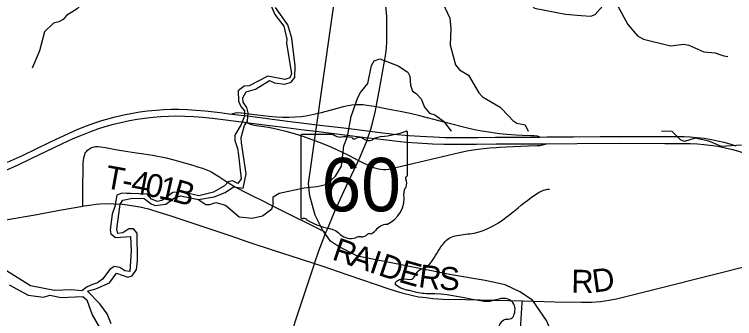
# Model space of a CAD drawing. Extents: x 0 to 34, y 0 to 22.
# Drawn here: x 4.8 to 6.577, y 15.488 to 16.238 of the extents above; entities that cross this region are included whole.
import ezdxf

# ---------------------------------------------------------------- set-up
doc = ezdxf.new("R2010")
doc.units = 0
for name, color, linetype in [('GM_X_County_Road', 7, 'Continuous'), ('GM_X_County_Road_Text', 7, 'Continuous'), ('GM_X_Interchange_Ramps', 7, 'Continuous'), ('GM_X_Minor_River', 7, 'Continuous'), ('GM_X_Rail_Line', 7, 'Continuous'), ('GM_X_State_Location', 7, 'Continuous'), ('GM_X_State_Route', 7, 'Continuous'), ('GM_X_State_Shield', 7, 'Continuous'), ('GM_X_Township_Road', 7, 'Continuous'), ('GM_X_Township_Road_Text', 7, 'Continuous')]:
    doc.layers.add(name, color=color, linetype=linetype)

msp = doc.modelspace()

# ---------------------------------------------------------------- linework, layer by layer
at = {"layer": 'GM_X_County_Road'}
for points in [[(4.2337, 15.6322), (4.2931, 15.6431), (4.4857, 15.6775), (4.6018, 15.6992), (4.6966, 15.7158), (4.7485, 15.7255), (4.7882, 15.7329), (4.8463, 15.7434), (4.9165, 15.7564), (4.9688, 15.7656)], [(4.9688, 15.7656), (4.9722, 15.7662), (4.9911, 15.769), (5.0017, 15.7704), (5.0113, 15.771), (5.0239, 15.7716), (5.0456, 15.7714), (5.0672, 15.7701), (5.0783, 15.7688), (5.0884, 15.7674), (5.0996, 15.7655), (5.1101, 15.7637), (5.1312, 15.7588), (5.141, 15.7557), (5.1518, 15.7525), (5.1861, 15.7413), (5.3317, 15.6927), (5.3758, 15.6777), (5.4436, 15.6552), (5.5029, 15.6367), (5.5408, 15.6243)], [(6.0536, 15.5319), (6.1339, 15.5298), (6.1992, 15.5286), (6.2241, 15.529), (6.2458, 15.5306), (6.2674, 15.5335), (6.2888, 15.5378), (6.3973, 15.5647), (6.6263, 15.6221), (6.7469, 15.6522), (6.8373, 15.6746), (6.913, 15.6935)], [(5.5408, 15.6243), (5.559, 15.6184), (5.6205, 15.5966), (5.7265, 15.5608), (5.7562, 15.5518), (5.7834, 15.545), (5.7975, 15.5422), (5.808, 15.5408), (5.8218, 15.539), (5.8327, 15.5378), (5.8575, 15.5361), (5.9134, 15.5349), (6.019, 15.5328), (6.0536, 15.5319)], [(6.0456, 15.4154), (6.0457, 15.4174), (6.0482, 15.4483), (6.0533, 15.5269), (6.0536, 15.5319)]]:
    msp.add_lwpolyline(points, dxfattribs=at)
at = {"layer": 'GM_X_Interchange_Ramps'}
for points in [[(5.6926, 16.0099), (5.6819, 16.0118), (5.6697, 16.0139), (5.6604, 16.015), (5.6511, 16.0156), (5.6418, 16.0154), (5.6325, 16.0145), (5.6233, 16.013), (5.6112, 16.0104), (5.5872, 16.0039), (5.5572, 15.9957), (5.5391, 15.9913), (5.5238, 15.9882), (5.5085, 15.9858), (5.493, 15.9844), (5.4775, 15.9838), (5.462, 15.9841), (5.4465, 15.985), (5.4279, 15.9868), (5.386, 15.9916), (5.3602, 15.9949), (5.3515, 15.9955), (5.3453, 15.9947), (5.3366, 15.9924)], [(6.0961, 15.9358), (6.0907, 15.9377), (6.0822, 15.9388), (6.0743, 15.939), (6.0536, 15.9394), (6.0369, 15.9401), (6.0153, 15.9418), (5.9968, 15.9438), (5.9753, 15.9467), (5.9538, 15.9502), (5.9356, 15.9538), (5.9145, 15.9586), (5.8694, 15.9701), (5.8005, 15.9882), (5.7764, 15.994), (5.7521, 15.999), (5.7338, 16.0023), (5.7124, 16.006), (5.6926, 16.0099)], [(5.3737, 15.9714), (5.3799, 15.9682), (5.385, 15.9671), (5.3969, 15.9646), (5.4157, 15.9621), (5.4309, 15.9593), (5.449, 15.9553), (5.47, 15.9501), (5.4908, 15.9443), (5.5115, 15.9379), (5.5319, 15.9308), (5.5522, 15.9232), (5.575, 15.9138), (5.5948, 15.905), (5.6227, 15.8918), (5.6492, 15.878)], [(5.9889, 15.9104), (5.9968, 15.911), (6.031, 15.9127), (6.0683, 15.9138), (6.0898, 15.9147), (6.0962, 15.9151), (6.1031, 15.9162), (6.1065, 15.917), (6.1126, 15.9191)], [(5.6492, 15.878), (5.661, 15.8725), (5.6807, 15.8633), (5.6864, 15.861), (5.6923, 15.859), (5.6983, 15.8575), (5.7045, 15.8565), (5.7106, 15.856), (5.7169, 15.8561), (5.723, 15.8567), (5.7292, 15.8576), (5.7413, 15.8603), (5.7866, 15.8712), (5.8984, 15.8979), (5.9166, 15.9017), (5.9319, 15.9044), (5.9504, 15.9069), (5.972, 15.9091), (5.9889, 15.9104)]]:
    msp.add_lwpolyline(points, dxfattribs=at)
at = {"layer": 'GM_X_Minor_River'}
for points in [[(5.0834, 16.345), (5.0529, 16.3383), (5.0294, 16.3291), (5.003, 16.307), (4.9894, 16.2998), (4.9793, 16.2865), (4.9684, 16.2644), (4.9552, 16.2522), (4.9291, 16.2358), (4.9205, 16.2259), (4.9095, 16.2195), (4.8971, 16.2168), (4.8748, 16.1951), (4.8618, 16.1487), (4.8438, 16.1054)], [(5.8108, 16.3252), (5.8511, 16.2789), (5.8741, 16.2285), (5.8768, 16.2035), (5.8755, 16.1629), (5.8828, 16.1356), (5.8882, 16.1136), (5.8984, 16.1015), (5.9201, 16.0883), (5.9456, 16.0451), (5.9551, 16.0349), (5.9984, 16.0093), (6.0201, 15.987), (6.0296, 15.9764), (6.0398, 15.9703), (6.0599, 15.9662), (6.0676, 15.9499)], [(6.038, 16.3192), (6.065, 16.2743), (6.0837, 16.2539), (6.1598, 16.2386), (6.1981, 16.2353), (6.2223, 16.2339), (6.2333, 16.2377), (6.2521, 16.259), (6.2623, 16.2655), (6.274, 16.267), (6.2884, 16.2599), (6.3136, 16.2129), (6.3372, 16.1857), (6.352, 16.177), (6.4191, 16.1609), (6.452, 16.1648), (6.4641, 16.1626), (6.5013, 16.146), (6.5293, 16.1435), (6.5407, 16.139), (6.5506, 16.136), (6.5604, 16.1341)], [(5.426, 16.277), (5.4425, 16.2376), (5.4649, 16.2089), (5.4726, 16.1767), (5.4719, 16.1672), (5.484, 16.0913), (5.4795, 16.0818), (5.4678, 16.0776), (5.4257, 16.0858), (5.3792, 16.0622), (5.3668, 16.061), (5.3524, 16.0495), (5.3529, 16.0245), (5.3586, 16.0109), (5.3678, 16.0003), (5.3678, 15.9874), (5.3596, 15.9669), (5.3442, 15.9406), (5.3442, 15.9274), (5.3508, 15.9077), (5.3519, 15.8974), (5.3594, 15.833), (5.3515, 15.8215), (5.3382, 15.8276), (5.3276, 15.8253), (5.3186, 15.8157), (5.2918, 15.8001), (5.2555, 15.7905), (5.2134, 15.8006), (5.1915, 15.7994), (5.1658, 15.7803), (5.153, 15.7769), (5.1389, 15.7829)], [(5.0388, 15.4749), (5.0288, 15.5002), (5.0113, 15.5245), (4.9809, 15.5558), (5.0009, 15.5612), (5.035, 15.5765), (5.0519, 15.6001), (5.0803, 15.59), (5.0909, 15.5934), (5.1011, 15.609), (5.104, 15.631), (5.1033, 15.6985), (5.0942, 15.7091), (5.0825, 15.7095), (5.0681, 15.6999), (5.0556, 15.698), (5.0529, 15.7086), (5.061, 15.7705), (5.0674, 15.78), (5.0916, 15.785), (5.1204, 15.7843), (5.1378, 15.7711), (5.1477, 15.7666), (5.1738, 15.7705), (5.1953, 15.7857), (5.2104, 15.7911), (5.2544, 15.7818), (5.2934, 15.7883), (5.3202, 15.7991), (5.3409, 15.8132), (5.3644, 15.8098), (5.3722, 15.8451), (5.3605, 15.9217), (5.3597, 15.935), (5.3683, 15.9639), (5.3754, 15.9753), (5.3773, 15.9958), (5.3738, 16.0083), (5.3643, 16.0219), (5.3638, 16.0325), (5.3717, 16.047), (5.3952, 16.0539), (5.4295, 16.0756), (5.4417, 16.0696), (5.4674, 16.0659), (5.4829, 16.0709), (5.492, 16.0827), (5.4926, 16.1111), (5.4847, 16.1797), (5.4747, 16.2127), (5.4443, 16.2551)], [(5.2524, 15.7822), (5.2726, 15.7697), (5.2825, 15.7693), (5.2976, 15.7743), (5.3207, 15.7676), (5.3545, 15.7389), (5.3871, 15.7359), (5.4124, 15.7417), (5.4351, 15.7585), (5.4388, 15.7691), (5.4387, 15.7881), (5.4538, 15.7972), (5.5151, 15.8107), (5.5473, 15.8135), (5.5722, 15.8193), (5.582, 15.8292), (5.5926, 15.8394), (5.6068, 15.8642), (5.6131, 15.9139), (5.6224, 15.937), (5.6309, 15.9864), (5.6478, 16.0331), (5.6538, 16.0457), (5.6718, 16.0677), (5.6811, 16.1118), (5.6879, 16.1235), (5.7019, 16.1285), (5.747, 16.1112), (5.7709, 16.0961), (5.7755, 16.0859), (5.7771, 16.0635), (5.7821, 16.0487), (5.7916, 16.0435), (5.8041, 16.0299), (5.8118, 16.0094), (5.8243, 15.9943), (5.8376, 15.9905), (5.8585, 15.9747), (5.8775, 15.9504)], [(6.5943, 15.9161), (6.5447, 15.9125), (6.5136, 15.926), (6.4799, 15.9331), (6.4534, 15.9247), (6.4436, 15.9288), (6.4226, 15.9493), (6.3969, 15.9499)], [(5.1389, 15.7829), (5.1279, 15.7946), (5.087, 15.7967), (5.0772, 15.7967), (5.065, 15.7978), (5.0526, 15.7924), (5.0481, 15.7647), (5.0418, 15.7457), (5.0367, 15.7074), (5.0382, 15.6972), (5.0496, 15.6877), (5.0864, 15.6908), (5.0882, 15.655), (5.0852, 15.6044), (5.0727, 15.6059), (5.0605, 15.6138), (5.0461, 15.6168), (5.0359, 15.6095), (5.0179, 15.5856), (5.0054, 15.5764), (4.9933, 15.5718), (4.9797, 15.5665), (4.9665, 15.5562), (4.9408, 15.5587), (4.8988, 15.5575), (4.8397, 15.569), (4.8203, 15.5811), (4.747, 15.6267)], [(4.787, 15.5715), (4.8345, 15.5458), (4.872, 15.5407), (4.8878, 15.5457), (4.9159, 15.5404), (4.9689, 15.5425), (4.9791, 15.5346), (4.9921, 15.4975), (5.028, 15.4346)]]:
    msp.add_lwpolyline(points, dxfattribs=at)
msp.add_spline([(5.6783, 14.4209), (5.6754, 14.4455), (5.659, 14.4864), (5.6554, 14.5103), (5.6393, 14.5702), (5.6236, 14.6069), (5.6144, 14.6437), (5.5991, 14.6824), (5.5748, 14.6842), (5.5627, 14.6803), (5.5472, 14.6814), (5.537, 14.6878), (5.5039, 14.7234), (5.503, 14.737), (5.5034, 14.7518), (5.5108, 14.7826), (5.5096, 14.8019), (5.5173, 14.8585), (5.5353, 14.8885), (5.5764, 14.9217), (5.5881, 14.9323), (5.6085, 14.9567), (5.6099, 14.9817), (5.6832, 15.0036), (5.6759, 15.0453), (5.6722, 15.1143), (5.6743, 15.2396), (5.6809, 15.2885), (5.6899, 15.3106), (5.6985, 15.3235), (5.7094, 15.333), (5.7276, 15.3331), (5.7382, 15.3376), (5.7483, 15.3616), (5.7616, 15.3643), (5.7869, 15.3625), (5.7895, 15.3769), (5.7967, 15.3891), (5.8269, 15.3888), (5.8833, 15.3985), (5.8977, 15.3981), (5.9257, 15.4096), (5.96, 15.4325), (5.9879, 15.4542), (6.0116, 15.4865), (6.0256, 15.4881), (6.0335, 15.4988), (6.0273, 15.5306), (6.0114, 15.5378), (5.9679, 15.53), (5.9547, 15.5311), (5.8376, 15.5489), (5.8028, 15.5507), (5.7774, 15.5567), (5.7679, 15.5586), (5.7406, 15.5763), (5.7557, 15.5862), (5.7807, 15.5851), (5.7991, 15.6076), (5.8142, 15.6141), (5.8248, 15.6229), (5.8526, 15.6651), (5.8764, 15.6883), (5.8923, 15.6933), (5.9343, 15.6991), (6.0268, 15.748), (6.0921, 15.7979), (6.1098, 15.8059), (6.1204, 15.8075)], degree=3, dxfattribs=at)
at = {"layer": 'GM_X_Rail_Line'}
msp.add_lwpolyline([(6.2556, 15.134), (6.2417, 15.1773), (6.1822, 15.3213), (6.1133, 15.4834), (6.0786, 15.5335), (6.047, 15.5543), (6.0111, 15.5713), (5.9614, 15.5818), (5.8784, 15.5959), (5.6469, 15.6419), (5.6002, 15.6656), (5.5803, 15.6787), (5.5601, 15.707), (5.5421, 15.7435), (5.5292, 15.7911), (5.526, 15.8216), (5.5991, 16.337)], dxfattribs=at)
at = {"layer": 'GM_X_State_Route'}
for points in [[(5.719, 16.1697), (5.7194, 16.1783), (5.7192, 16.2219), (5.7187, 16.233), (5.7177, 16.2507), (5.716, 16.2654), (5.7131, 16.2807), (5.709, 16.2957), (5.7037, 16.3104), (5.6933, 16.3346)], [(5.6926, 16.0099), (5.6999, 16.0493), (5.7162, 16.1411), (5.7173, 16.1489), (5.7179, 16.1547), (5.7185, 16.1598), (5.7189, 16.1668), (5.719, 16.1697)], [(5.6693, 15.9259), (5.6725, 15.9341), (5.6778, 15.9501), (5.6795, 15.9551), (5.6846, 15.9731), (5.6909, 16.0004), (5.6926, 16.0099)], [(4.7836, 15.8736), (4.8203, 15.8906), (4.8875, 15.9229), (4.9352, 15.9453), (4.9551, 15.954), (4.9782, 15.9632), (4.9986, 15.9706), (5.0162, 15.9763), (5.0341, 15.9815), (5.0491, 15.9854), (5.0703, 15.9903), (5.0915, 15.9947), (5.1099, 15.9977), (5.1283, 16.0002), (5.1499, 16.0023), (5.1684, 16.0036), (5.187, 16.0042), (5.2056, 16.0043), (5.2273, 16.0037), (5.249, 16.0024), (5.2706, 16.0004), (5.3076, 15.996), (5.3292, 15.9933), (5.3366, 15.9924), (5.3815, 15.9871), (5.4246, 15.9814), (5.4678, 15.9761), (5.514, 15.9704), (5.5541, 15.9653), (5.6127, 15.9581), (5.6778, 15.9501), (5.6959, 15.9479), (5.736, 15.9432), (5.7731, 15.9397), (5.801, 15.9376), (5.8352, 15.9359), (5.8631, 15.935), (5.8942, 15.9347), (5.9439, 15.9348), (5.9874, 15.9351), (6.0681, 15.9357), (6.0961, 15.9358), (6.1147, 15.9359), (6.1799, 15.9364), (6.2451, 15.9369), (6.2917, 15.9372), (6.4151, 15.9373), (6.4305, 15.9373), (6.4522, 15.937), (6.4676, 15.9363), (6.4831, 15.935), (6.5015, 15.9328), (6.5199, 15.9299), (6.535, 15.9268), (6.5501, 15.9232), (6.565, 15.919), (6.5798, 15.9144)], [(4.774, 15.8517), (4.808, 15.8668), (4.8418, 15.8825), (4.9173, 15.9189), (4.9456, 15.9318), (4.9684, 15.9416), (4.9887, 15.9496), (5.0062, 15.9559), (5.024, 15.9615), (5.045, 15.9675), (5.0631, 15.9719), (5.0844, 15.9764), (5.1028, 15.9797), (5.1212, 15.9823), (5.1428, 15.9848), (5.1614, 15.9864), (5.1801, 15.9873), (5.1987, 15.9877), (5.2205, 15.9874), (5.2422, 15.9864), (5.2639, 15.9846), (5.2886, 15.982), (5.3737, 15.9714), (5.3842, 15.9701), (5.4304, 15.9645), (5.4705, 15.9595), (5.5074, 15.9547), (5.5505, 15.9491), (5.6536, 15.9365)], [(5.5408, 15.6243), (5.5514, 15.6553), (5.5689, 15.7002), (5.5717, 15.7074), (5.5911, 15.7531), (5.6127, 15.8013), (5.6395, 15.8574), (5.6492, 15.878), (5.6514, 15.8827), (5.6625, 15.9084), (5.6693, 15.9259)], [(5.6536, 15.9365), (5.6725, 15.9341), (5.6831, 15.9328), (5.7386, 15.9262), (5.7664, 15.9234), (5.7942, 15.9213), (5.8314, 15.9192), (5.8593, 15.9183), (5.8904, 15.9179), (5.94, 15.9183), (5.9897, 15.9189), (6.1015, 15.9191), (6.1126, 15.9191), (6.1885, 15.9196), (6.2941, 15.9203), (6.4046, 15.9201), (6.4452, 15.9202), (6.4629, 15.9199)], [(6.4629, 15.9199), (6.467, 15.9198), (6.4857, 15.9189), (6.5013, 15.9176), (6.5168, 15.9158), (6.5353, 15.9129), (6.5507, 15.91), (6.5689, 15.9059), (6.584, 15.9017), (6.5989, 15.897), (6.6136, 15.8918), (6.6244, 15.8875), (6.6548, 15.8741), (6.6635, 15.8707), (6.6671, 15.8696), (6.6727, 15.8688)], [(5.4846, 15.4549), (5.4999, 15.5022), (5.5402, 15.623), (5.5408, 15.6243)]]:
    msp.add_lwpolyline(points, dxfattribs=at)
at = {"layer": 'GM_X_State_Shield'}
for p, q in [((5.5067, 15.9386), (5.5067, 15.7385)), ((5.5865, 15.9421), (5.5093, 15.9421)), ((5.7704, 15.8423), (5.7704, 15.947)), ((5.7704, 15.8424), (5.7704, 15.8423))]:
    msp.add_line(p, q, dxfattribs=at)
for centre, radius, start, end in [((5.5097, 15.939), 0.00305, 98.1301, 188.1301), ((5.6049, 15.9653), 0.0296, 231.6195, 271.1119), ((5.7121, 15.8809), 0.0563, 97.3462, 120.7689), ((5.6765, 16.2149), 0.2796, 275.8445, 288.9065), ((5.7675, 15.9475), 0.00294, 351.8621, 97.738), ((5.6147, 15.8297), 0.1064, 80.4867, 94.9883), ((5.6389, 15.9401), 0.00855, 219.7921, 297.1024), ((5.6514, 15.917), 0.0178, 54.4667, 119.1411), ((5.6744, 15.9487), 0.0214, 233.8562, 294.8282), ((5.7697, 15.8347), 0.00454, 107.944, 210.337), ((5.7408, 15.8214), 0.0273, 340.033, 23.6496), ((5.7672, 15.8419), 0.00314, 289.6038, 7.7341), ((5.6921, 15.7852), 0.0699, 292.3089, 8.9858), ((5.7809, 15.7985), 0.0198, 136.8065, 186.9296), ((5.5098, 15.7381), 0.00308, 171.9584, 258.3066), ((5.5102, 15.7585), 0.0235, 267.339, 280.6039), ((5.515, 15.727), 0.00848, 29.7484, 93.2717), ((5.6221, 15.9068), 0.2019, 240.4129, 257.1985), ((5.5619, 15.6486), 0.0632, 47.1842, 75.836), ((5.7216, 15.6823), 0.0383, 94.4031, 142.5768), ((5.6302, 15.726), 0.0401, 230.7004, 286.2918), ((5.6534, 15.6568), 0.0329, 85.6951, 111.2099), ((5.6563, 15.711), 0.0214, 268.777, 315.5493), ((5.6756, 15.6916), 0.00601, 65.7517, 132.6484), ((5.6731, 15.7191), 0.0226, 282.8732, 323.2771)]:
    msp.add_arc(centre, radius, start, end, dxfattribs=at)
at = {"layer": 'GM_X_Township_Road'}
msp.add_lwpolyline([(4.9688, 15.7656), (4.9688, 15.7727), (4.9687, 15.7821), (4.9691, 15.8038), (4.9695, 15.8255), (4.9697, 15.8442), (4.9701, 15.8597), (4.9703, 15.872), (4.9706, 15.8782), (4.9716, 15.8842), (4.9728, 15.8902), (4.9739, 15.8931), (4.9752, 15.8959), (4.9769, 15.8985), (4.9788, 15.9009), (4.981, 15.9032), (4.9833, 15.9053), (4.9858, 15.9071), (4.9884, 15.9087), (4.9912, 15.91), (4.9942, 15.911), (4.9972, 15.9117), (5.0003, 15.9121), (5.0034, 15.9122), (5.0065, 15.9121), (5.0127, 15.9115), (5.0249, 15.9096), (5.0371, 15.9073), (5.0544, 15.9039), (5.0799, 15.9004), (5.1013, 15.897), (5.1197, 15.894), (5.1412, 15.8908), (5.175, 15.8843), (5.1935, 15.8795), (5.2049, 15.8763), (5.2345, 15.8684), (5.2433, 15.8655), (5.2522, 15.8626), (5.264, 15.8587), (5.2727, 15.8556), (5.2808, 15.8527), (5.2872, 15.8491), (5.2941, 15.8452), (5.3048, 15.8386), (5.3218, 15.8271), (5.3327, 15.8208), (5.3432, 15.8142), (5.354, 15.8081), (5.3678, 15.8009), (5.3955, 15.7871), (5.4066, 15.7816), (5.4371, 15.7661), (5.4899, 15.7399), (5.5235, 15.7237), (5.54, 15.7152), (5.5593, 15.7052), (5.5689, 15.7002)], dxfattribs=at)

# ---------------------------------------------------------------- texts
at = {"layer": 'GM_X_County_Road_Text'}
for s, rotation, p in [('R', 341.3194, (5.5815, 15.6347)), ('A', 341.3185, (5.6257, 15.6197)), ('I', 341.3182, (5.673, 15.6037)), ('D', 341.4596, (5.6953, 15.5962)), ('E', 344.1267, (5.7455, 15.5794)), ('R', 352.3702, (5.7951, 15.566)), ('S', 358.0633, (5.8475, 15.5593)), ('R', 359.317, (6.1739, 15.5519)), ('D', 7.9683, (6.2297, 15.5519))]:
    msp.add_text(s, height=0.0568, rotation=rotation, dxfattribs=at).set_placement(p)
at = {"layer": 'GM_X_State_Location'}
for s in ['s', 'r']:
    msp.add_text(s, height=0.000189, dxfattribs=at).set_placement((5.6356, 15.8253))
msp.add_text('60', height=0.000189, rotation=0, dxfattribs=at).set_placement((5.5879, 15.8115))
at = {"layer": 'GM_X_State_Shield'}
msp.add_text('60', height=0.13184, dxfattribs=at).set_placement((5.5577, 15.7526))
at = {"layer": 'GM_X_Township_Road_Text'}
for s, rotation, p in [('T', 349.6978, (5.0209, 15.8107)), ('4', 349.3014, (5.0856, 15.7989)), ('0', 348.3359, (5.1197, 15.7925)), ('1', 347.303, (5.1537, 15.7855)), ('B', 344.4519, (5.1872, 15.778)), ('-', 349.6163, (5.0627, 15.8031))]:
    msp.add_text(s, height=0.0568, rotation=rotation, dxfattribs=at).set_placement(p)

doc.saveas('drawing.dxf')
